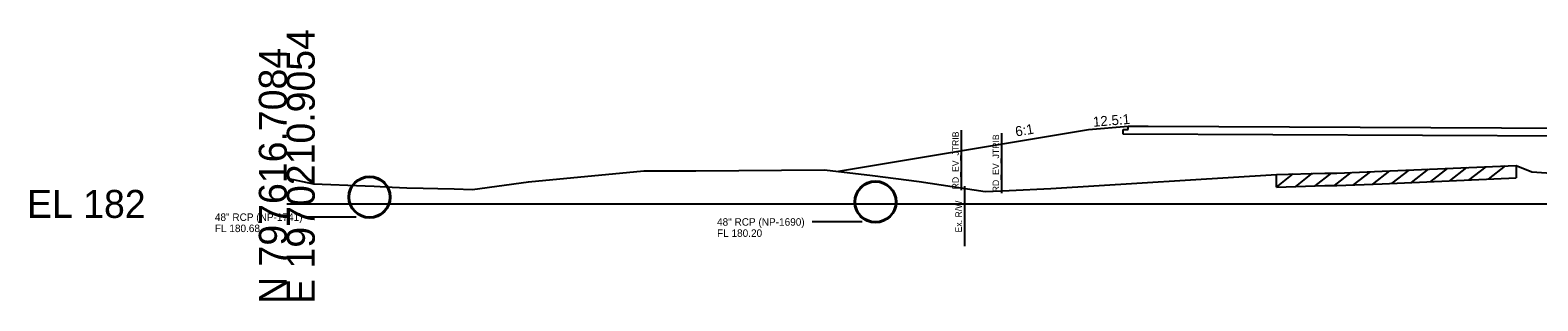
# Model space of a CAD drawing. Extents: x -26 to 303, y -10 to 1532.
# Drawn here: x -25.7 to 125.2, y 1490.3 to 1517.4 of the extents above; entities that cross this region are included whole.
import ezdxf

# ---------------------------------------------------------------- set-up
doc = ezdxf.new("R2010")
doc.units = 0
for name, color, linetype in [('RD_GPK_XS_Cell', 7, 'Continuous'), ('RD_XS_Base', 7, 'Continuous'), ('RD_XS_EarthShd', 7, 'Continuous'), ('RD_XS_ExGround', 7, 'Continuous'), ('RD_XS_ExPaveRet', 7, 'Continuous'), ('RD_XS_ExRW', 7, 'Continuous'), ('RD_XS_EXWetland', 7, 'Continuous'), ('RD_XS_Misc_Line', 7, 'Continuous'), ('RD_XS_Pave', 7, 'Continuous'), ('RD_XS_PaveShd', 7, 'Continuous'), ('RD_XS_Pipe', 7, 'Continuous'), ('RD_XS_TieSlope', 7, 'Continuous'), ('RD_XS_TX_ShdSlope', 7, 'Continuous'), ('RD_XS_TX_Slope', 7, 'Continuous')]:
    doc.layers.add(name, color=color, linetype=linetype)

msp = doc.modelspace()

# ---------------------------------------------------------------- linework, layer by layer
at = {"layer": 'RD_GPK_XS_Cell'}
msp.add_line((0, 1500), (150, 1500), dxfattribs=at)
at = {"layer": 'RD_XS_Base'}
for p, q in [((83.74, 1507.44), (84.24, 1507.44)), ((83.74, 1506.96), (83.74, 1507.44)), ((150, 1506.69), (83.74, 1506.96)), ((84.24, 1507.44), (84.24, 1507.74))]:
    msp.add_line(p, q, dxfattribs=at)
at = {"layer": 'RD_XS_EarthShd'}
msp.add_line((84.24, 1507.74), (80.24, 1507.42), dxfattribs=at)
at = {"layer": 'RD_XS_ExGround'}
msp.add_lwpolyline([(0, 1502.56), (2.67, 1502), (7.84, 1501.8), (8.76, 1501.76), (10.56, 1501.66), (12, 1501.62), (13.65, 1501.58), (15.12, 1501.55), (16.75, 1501.52), (18.58, 1501.43), (24.19, 1502.22), (35.75, 1503.32), (38.39, 1503.32), (40.95, 1503.32), (53.84, 1503.42), (58.62, 1502.84), (63.31, 1502.24), (69.92, 1501.23), (72.31, 1501.34), (76.48, 1501.53), (99.09, 1502.94), (103.92, 1503.09), (105.13, 1503.08), (109.65, 1503.27), (123.07, 1503.85), (124.65, 1503.2), (127.58, 1503.01)], dxfattribs=at)
at = {"layer": 'RD_XS_ExPaveRet'}
for p, q in [((123.07, 1503.85), (123.07, 1502.6)), ((99.09, 1501.69), (99.09, 1502.94)), ((99.09, 1501.69), (103.92, 1501.84)), ((103.92, 1501.84), (105.13, 1501.83)), ((105.13, 1501.83), (109.65, 1502.02)), ((109.65, 1502.02), (123.07, 1502.6))]:
    msp.add_line(p, q, dxfattribs=at)
at = {"layer": 'RD_XS_ExRW'}
msp.add_line((67.83, 1501.76), (67.83, 1495.76), dxfattribs=at)
at = {"layer": 'RD_XS_EXWetland'}
for p, q in [((67.52, 1507.38), (67.52, 1501.38)), ((71.56, 1507.09), (71.56, 1501.09))]:
    msp.add_line(p, q, dxfattribs=at)
at = {"layer": 'RD_XS_Misc_Line'}
for p, q in [((108.72, 1501.98), (110.42, 1503.3)), ((110.65, 1502.06), (112.35, 1503.38)), ((112.58, 1502.14), (114.28, 1503.47)), ((114.51, 1502.23), (116.21, 1503.55)), ((116.43, 1502.31), (118.13, 1503.64)), ((118.36, 1502.4), (120.06, 1503.72)), ((120.29, 1502.48), (121.99, 1503.81)), ((99.09, 1501.69), (100.76, 1503)), ((101.01, 1501.75), (102.69, 1503.06)), ((102.94, 1501.81), (104.58, 1503.09)), ((104.87, 1501.84), (106.54, 1503.14)), ((106.8, 1501.9), (108.49, 1503.22))]:
    msp.add_line(p, q, dxfattribs=at)
at = {"layer": 'RD_XS_Pave'}
msp.add_line((150, 1507.47), (86.24, 1507.73), dxfattribs=at)
at = {"layer": 'RD_XS_PaveShd'}
msp.add_line((86.24, 1507.73), (84.24, 1507.74), dxfattribs=at)
at = {"layer": 'RD_XS_Pipe'}
for p, q in [((6.95, 1498.68), (1.95, 1498.68)), ((57.59, 1498.2), (52.59, 1498.2))]:
    msp.add_line(p, q, dxfattribs=at)
for centre, radius in [((8.28, 1500.68), 2.1), ((8.28, 1500.68), 2), ((58.93, 1500.2), 2.1), ((58.93, 1500.2), 2)]:
    msp.add_circle(centre, radius, dxfattribs=at)
at = {"layer": 'RD_XS_TieSlope'}
msp.add_line((80.24, 1507.42), (55.24, 1503.25), dxfattribs=at)

# ---------------------------------------------------------------- texts
at = {"layer": 'RD_GPK_XS_Cell'}
for s, p in [('E 1970210.9054', (2.8, 1490)), ('N 797616.7084', (0, 1490))]:
    msp.add_text(s, height=2.8, rotation=90, dxfattribs=at).set_placement(p)
msp.add_text('EL 182', height=2.8, dxfattribs=at).set_placement((-26, 1498.6))
at = {"layer": 'RD_XS_ExRW'}
msp.add_text('Ex. R/W ', height=0.65, rotation=90, dxfattribs=at).set_placement((67.58, 1497.14))
at = {"layer": 'RD_XS_EXWetland'}
for p in [(67.27, 1501.45), (71.31, 1501.16)]:
    msp.add_text('RD_EV_JTRIB', height=0.65, rotation=90, dxfattribs=at).set_placement(p)
at = {"layer": 'RD_XS_Pipe'}
for s, p in [('48" RCP (NP-1741)', (-7.2, 1498.3)), ('FL 180.68', (-7.2, 1497.18)), ('48" RCP (NP-1690)', (43.07, 1497.82)), ('FL 180.20', (43.07, 1496.7))]:
    msp.add_text(s, height=0.75, dxfattribs=at).set_placement(p)
at = {"layer": 'RD_XS_TX_ShdSlope'}
msp.add_text('12.5:1', height=1, rotation=4.5739, dxfattribs=at).set_placement((80.74, 1507.71))
at = {"layer": 'RD_XS_TX_Slope'}
msp.add_text('6:1', height=1, rotation=9.4623, dxfattribs=at).set_placement((73.01, 1506.73))

doc.saveas('drawing.dxf')
